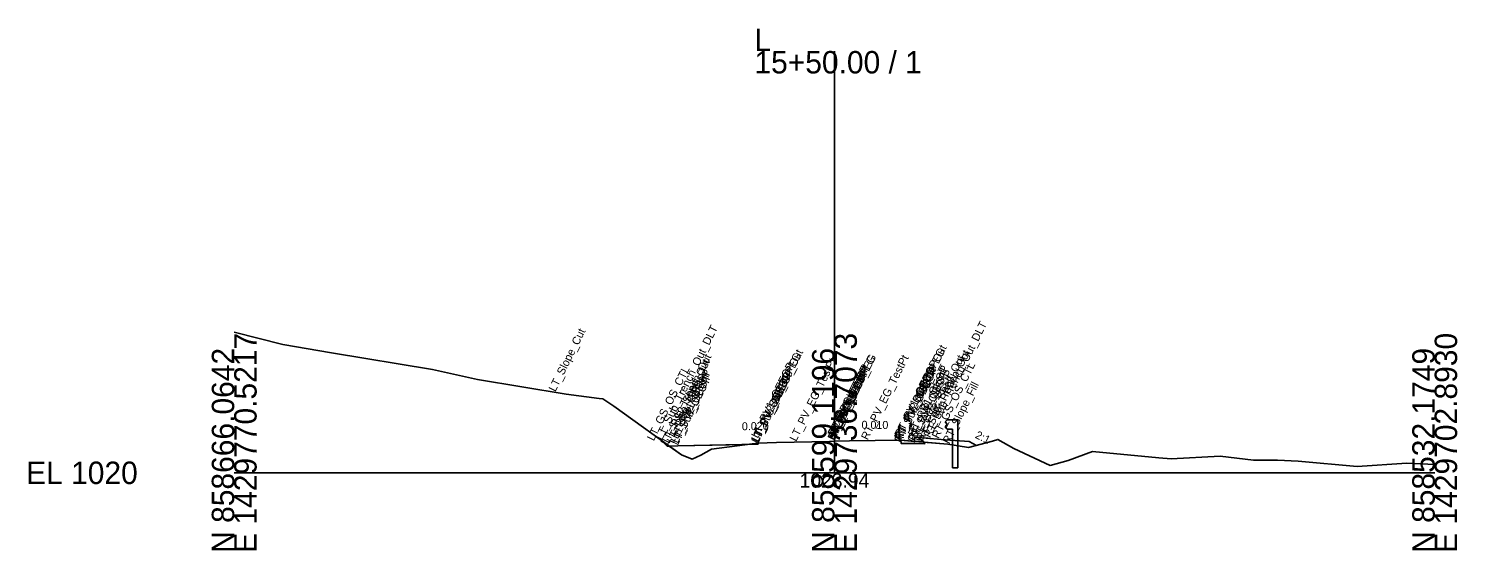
# Model space of a CAD drawing. Extents: x -26 to 176, y -10 to 13058.
# Drawn here: x -25.7 to 152.8, y 7990.3 to 8055.5 of the extents above; entities that cross this region are included whole.
import ezdxf

# ---------------------------------------------------------------- set-up
doc = ezdxf.new("R2010")
doc.units = 0
for name, color, linetype in [('Default', 7, 'Continuous'), ('Exist Cross Section Cell', 7, 'Continuous'), ('Exist XS Center Line Elevation Label', 7, 'Continuous'), ('Exist XS Ground Line', 7, 'Continuous'), ('Old_Level_50', 7, 'Continuous'), ('Prop CMT Guardrail Graphics', 7, 'Continuous'), ('Prop CMT Pvmt Course 1', 7, 'Continuous'), ('Prop CMT Pvmt Course 2', 7, 'Continuous'), ('Prop CMT Pvmt Surface Shoulder', 7, 'Continuous'), ('Prop CMT Pvmt Wedge Surface 1', 7, 'Continuous'), ('Prop CMT Pvmt Wedge Surface 2', 7, 'Continuous'), ('Prop CMT Shld Paved Course 1', 7, 'Continuous'), ('Prop CMT Shld Paved Course 2', 7, 'Continuous'), ('Prop CMT Slope Grass', 7, 'Continuous'), ('Prop CMT Subgrade Earthwork', 7, 'Continuous'), ('Prop XS Dump Level', 7, 'Continuous'), ('Prop XS SE Text', 7, 'Continuous'), ('Prop XS Side Slope Text', 7, 'Continuous')]:
    doc.layers.add(name, color=color, linetype=linetype)

msp = doc.modelspace()

# ---------------------------------------------------------------- linework, layer by layer
at = {"layer": 'Exist Cross Section Cell'}
for p, q in [((75, 8000), (75, 8052.69)), ((0, 8000), (75, 8000)), ((75, 8000), (150, 8000))]:
    msp.add_line(p, q, dxfattribs=at)
at = {"layer": 'Exist XS Ground Line'}
msp.add_lwpolyline([(0, 8017.56), (6.09, 8016.04), (12.14, 8014.99), (24.78, 8012.9), (30.42, 8011.64), (41.48, 8009.84), (45.59, 8009.28), (46.05, 8009.25), (47.45, 8008.32), (55.89, 8002.24), (57.23, 8001.69), (58.31, 8002.21), (59.63, 8002.97), (62.85, 8003.39), (65.44, 8003.71), (67.74, 8003.79), (74.37, 8003.92), (75, 8003.94), (76.86, 8003.99), (83.31, 8004.08), (89.18, 8003.56), (91.75, 8003.15), (94.74, 8003.97), (95.43, 8004.17), (97.42, 8003.03), (101.94, 8000.92), (104.21, 8001.52), (107.25, 8002.67), (115.54, 8001.88), (117.09, 8001.76), (123.2, 8002.08), (127.37, 8001.6), (130.36, 8001.57), (132.94, 8001.47), (140.33, 8000.79), (146.53, 8001.19), (150, 8001.05)], dxfattribs=at)
at = {"layer": 'Old_Level_50'}
for points in [[(53.44, 8004.01), (54.36, 8003.34), (54.11, 8003.34)], [(54.11, 8003.34), (54.36, 8003.34), (53.44, 8004.01)], [(64.02, 8003.53), (65.44, 8003.71), (65.46, 8003.71), (65.44, 8003.56)], [(65.44, 8003.56), (65.46, 8003.71), (65.44, 8003.71), (64.02, 8003.53)], [(85, 8003.65), (83.32, 8003.67), (83.3, 8004.08), (85, 8003.93), (85, 8003.9), (85.38, 8003.9), (86.1, 8003.83), (86.31, 8003.63)], [(83.32, 8003.67), (83.3, 8004.08), (85, 8003.93), (85, 8003.9), (85.38, 8003.9), (86.1, 8003.83), (86.31, 8003.63), (85, 8003.65)], [(88.82, 8004.14), (91.82, 8003.9), (92.76, 8003.43), (91.75, 8003.15), (89.18, 8003.56), (86.1, 8003.83), (86.05, 8003.88), (85.55, 8003.89), (85.38, 8003.9), (85, 8003.93), (85, 8004.44)], [(85, 8004.44), (85, 8003.93), (85.38, 8003.9), (85.55, 8003.89), (86.05, 8003.88), (86.1, 8003.83), (89.18, 8003.56), (91.75, 8003.15), (92.76, 8003.43), (91.82, 8003.9), (88.82, 8004.14)], [(85, 8003.93), (85.38, 8003.9), (85, 8003.9)], [(85.38, 8003.9), (85, 8003.9), (85, 8003.93)], [(57.23, 8001.69), (58.31, 8002.21), (59.63, 8002.97), (62.85, 8003.39), (64.02, 8003.53), (55.42, 8003.36), (54.36, 8003.34), (55.89, 8002.24)], [(54.36, 8003.34), (55.89, 8002.24), (57.23, 8001.69), (58.31, 8002.21), (59.63, 8002.97), (62.85, 8003.39), (64.02, 8003.53), (55.42, 8003.36)]]:
    msp.add_lwpolyline(points, close=True, dxfattribs=at)
at = {"layer": 'Prop CMT Guardrail Graphics'}
for points in [[(90.42, 8006.64), (89.09, 8006.64), (88.82, 8006.35)], [(88.82, 8006.35), (89.09, 8006.06)], [(89.09, 8006.06), (88.82, 8005.76)], [(88.82, 8005.76), (89.09, 8005.47), (89.76, 8005.47)], [(89.76, 8005.47), (89.76, 8000.64)], [(90.42, 8000.64), (90.42, 8006.64)], [(89.76, 8000.64), (90.42, 8000.64)]]:
    msp.add_lwpolyline(points, dxfattribs=at)
at = {"layer": 'Prop CMT Pvmt Course 1'}
msp.add_lwpolyline([(85, 8004.44), (85, 8003.9)], dxfattribs=at)
at = {"layer": 'Prop CMT Pvmt Course 2'}
for points in [[(85, 8003.65), (83.32, 8003.67)], [(55.42, 8003.36), (65.44, 8003.56)]]:
    msp.add_lwpolyline(points, dxfattribs=at)
at = {"layer": 'Prop CMT Pvmt Surface Shoulder'}
msp.add_lwpolyline([(85, 8004.44), (85, 8004.44)], dxfattribs=at)
at = {"layer": 'Prop CMT Pvmt Wedge Surface 1'}
msp.add_lwpolyline([(85, 8003.9), (85, 8004.44)], dxfattribs=at)
at = {"layer": 'Prop CMT Pvmt Wedge Surface 2'}
msp.add_lwpolyline([(85, 8003.9), (85, 8004.44)], dxfattribs=at)
at = {"layer": 'Prop CMT Shld Paved Course 1'}
for points in [[(85, 8004.44), (85, 8004.44)], [(85, 8003.9), (85, 8004.44)], [(85.55, 8003.89), (85, 8003.9)]]:
    msp.add_lwpolyline(points, dxfattribs=at)
at = {"layer": 'Prop CMT Shld Paved Course 2'}
for points in [[(85, 8003.9), (85.55, 8003.89), (86.05, 8003.88), (86.31, 8003.63)], [(86.31, 8003.63), (85, 8003.65)], [(54.11, 8003.34), (55.42, 8003.36)]]:
    msp.add_lwpolyline(points, dxfattribs=at)
at = {"layer": 'Prop CMT Slope Grass'}
for points in [[(85, 8004.44), (88.82, 8004.14)], [(88.82, 8004.14), (91.82, 8003.9)], [(91.82, 8003.9), (92.76, 8003.43)]]:
    msp.add_lwpolyline(points, dxfattribs=at)
at = {"layer": 'Prop CMT Subgrade Earthwork'}
for points in [[(54.11, 8003.34), (53.44, 8004.01)], [(65.44, 8003.56), (65.46, 8003.71)], [(83.32, 8003.67), (83.3, 8004.08)], [(83.32, 8003.67), (85, 8003.65)], [(85, 8003.65), (86.31, 8003.63)], [(55.42, 8003.36), (54.11, 8003.34)], [(65.44, 8003.56), (55.42, 8003.36)]]:
    msp.add_lwpolyline(points, dxfattribs=at)

# ---------------------------------------------------------------- texts
at = {"layer": 'Default'}
msp.add_text('-', height=0.0001, dxfattribs=at).set_placement((0, 8000))
at = {"layer": 'Exist Cross Section Cell'}
for s, p in [('L', (65, 8052.69)), ('15+50.00 / 1', (65, 8049.89)), ('EL 1020', (-26, 7998.6))]:
    msp.add_text(s, height=2.8, dxfattribs=at).set_placement(p)
for s, p in [('E 1429770.5217', (2.8, 7990)), ('E 1429736.7073', (77.8, 7990)), ('E 1429702.8930', (152.8, 7990)), ('N 858666.0642', (0, 7990)), ('N 858599.1196', (75, 7990)), ('N 858532.1749', (150, 7990))]:
    msp.add_text(s, height=2.8, rotation=90, dxfattribs=at).set_placement(p)
at = {"layer": 'Exist XS Center Line Elevation Label'}
msp.add_text('1023.94', height=1.8, dxfattribs=at).set_placement((70.65, 7998.14))
msp.add_text('1023.94', height=1.8, dxfattribs=at).set_placement((70.65, 7998.14))
msp.add_text('1023.94', height=1.8, dxfattribs=at).set_placement((70.65, 7998.14))
at = {"layer": 'Prop XS Dump Level'}
for s, p in [('LT_Slope_Cut', (40.12, 8010.06)), ('LT_Slope_Cut', (40.12, 8010.06)), ('LT_Sub_Trench_Out_DLT', (53.45, 8004)), ('RT_Sub_Trench_Out_DLT', (86.97, 8004.29)), ('LT_Sub_Trench_Out', (54.11, 8003.34)), ('LT_PV_OEEOP_EG', (65.44, 8003.71)), ('LT_PV_Sub_Tie_Out', (65.46, 8003.71)), ('LT_PV_EG_TestPt', (70.22, 8003.84)), ('RT_PV_IEEOP_EG', (75, 8003.94)), ('LT_PV_IEEOP_EG', (75, 8003.94)), ('RT_PV_EG_TestPt', (79.16, 8004.02)), ('RT_PV_Sub_Tie_Out', (83.3, 8004.08)), ('RT_PV_OEEOP_EG', (83.32, 8004.08)), ('RT_PS2_Shelf_Out', (86.05, 8003.88)), ('RT_Sub_Trench_Out', (86.31, 8003.63)), ('LT_GS_OS_CTL', (52.42, 8003.91)), ('LT_PS2_Shelf_Out', (54.36, 8003.59)), ('LT_PV1_OEOT', (55.42, 8004.15)), ('LT_PS1_OEOP', (55.42, 8004.15)), ('LT_PV1_OEEOP', (65.44, 8004.23)), ('LT_PV2_OEEOP', (65.44, 8003.81)), ('LT_Sub_OEEOP', (65.44, 8003.56)), ('RT_PV1_IEEOP', (75, 8004.42)), ('LT_PV1_IEEOP', (75, 8004.42)), ('RT_PV2_IEEOP', (75, 8004)), ('LT_PV2_IEEOP', (75, 8004)), ('RT_PV1_OEEOP', (83.32, 8004.34)), ('RT_PV2_OEEOP', (83.32, 8003.92)), ('RT_Sub_OEEOP', (83.32, 8003.67)), ('RT_PV1_OEOT', (85, 8004.44)), ('RT_PS1_OEOP', (85, 8004.44)), ('RT_PV2_OEOT', (85, 8003.9)), ('RT_PS2_OEOP', (85.55, 8003.89)), ('RT_GS_OS_CTL', (88, 8004.2)), ('LT_PS2_OEOP', (54.86, 8003.6)), ('LT_PV2_OEOT', (55.42, 8003.61)), ('LT_Sub_OEOT', (55.42, 8003.36)), ('RT_Sub_OEOT', (85, 8003.65)), ('RT_Slope_Fill', (89.34, 8003.53)), ('PV1_PGL', (75, 8004.54)), ('PV2_PGL', (75, 8004))]:
    msp.add_text(s, height=1, rotation=63.5833, dxfattribs=at).set_placement(p)
at = {"layer": 'Prop XS SE Text'}
for s, rotation, p in [('0.020', 1.1458, (63.44, 8005.31)), ('0.010', 359.4271, (78.38, 8005.51))]:
    msp.add_text(s, height=1, rotation=rotation, dxfattribs=at).set_placement(p)
at = {"layer": 'Prop XS Side Slope Text'}
msp.add_text('2:1', height=1, rotation=333.4349, dxfattribs=at).set_placement((92.5, 8004.4))

doc.saveas('drawing.dxf')
